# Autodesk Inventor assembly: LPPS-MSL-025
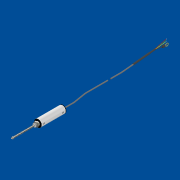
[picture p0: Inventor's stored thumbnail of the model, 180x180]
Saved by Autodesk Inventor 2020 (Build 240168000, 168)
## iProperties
Created: 2019-07
Part Number: LPPS-MSL-025
Document SubType Name: Assembly
Designer: J. Nielson
Author: J. Nielson
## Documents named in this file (5)
- D:\Users\Justin\Documents\CAD Drawings\The Sensor Connection\LPPS\LPPS-MSL\3D\LPPS-MSL-025\LPPS-MSL-025.iam
- D:\Users\Justin\Documents\CAD Drawings\The Sensor Connection\LPPS\LPPS-MSL\3D\LPPS-MSL-025\LPPS-MSL-025 HOUSING_SW.ipt
- D:\Users\Justin\Documents\CAD Drawings\The Sensor Connection\LPPS\LPPS-MSL\3D\LPPS-MSL-025\LPPS-MSL-025 SHAFT_SW.ipt
- D:\Users\Justin\Documents\CAD Drawings\The Sensor Connection\LPPS\LPPS-MSL\3D\MSL PARTS\ISO 4035 - M8BS EN.ipt
- D:\Users\Justin\Documents\CAD Drawings\The Sensor Connection\LPPS\LPPS-MSL\3D\LPPS-MSL-025\LPPS-MSL-025 Spring.ipt
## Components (4 placed, 4 different names)
1. LPPS-MSL-025 HOUSING_SW:1 — Mate:1, Stroke, Mate:3, Flush:1
2. LPPS-MSL-025 SHAFT_SW:1 — Mate:1, Stroke
3. ISO 4035 - M8BS EN:1 — Mate:3, Angle:1, Flush:1
4. LPPS-MSL-025 Spring:1 — Flush:2
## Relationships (6: Mate 3, Flush 2, Angle 1)
- Mate:1: LPPS-MSL-025 HOUSING_SW:1 ↔ LPPS-MSL-025 SHAFT_SW:1
- Stroke [Mate]: LPPS-MSL-025 HOUSING_SW:1 ↔ LPPS-MSL-025 SHAFT_SW:1
- Mate:3: LPPS-MSL-025 HOUSING_SW:1 ↔ ISO 4035 - M8BS EN:1
- Angle:1: ISO 4035 - M8BS EN:1
- Flush:1: LPPS-MSL-025 HOUSING_SW:1 ↔ ISO 4035 - M8BS EN:1
- Flush:2: LPPS-MSL-025 Spring:1
